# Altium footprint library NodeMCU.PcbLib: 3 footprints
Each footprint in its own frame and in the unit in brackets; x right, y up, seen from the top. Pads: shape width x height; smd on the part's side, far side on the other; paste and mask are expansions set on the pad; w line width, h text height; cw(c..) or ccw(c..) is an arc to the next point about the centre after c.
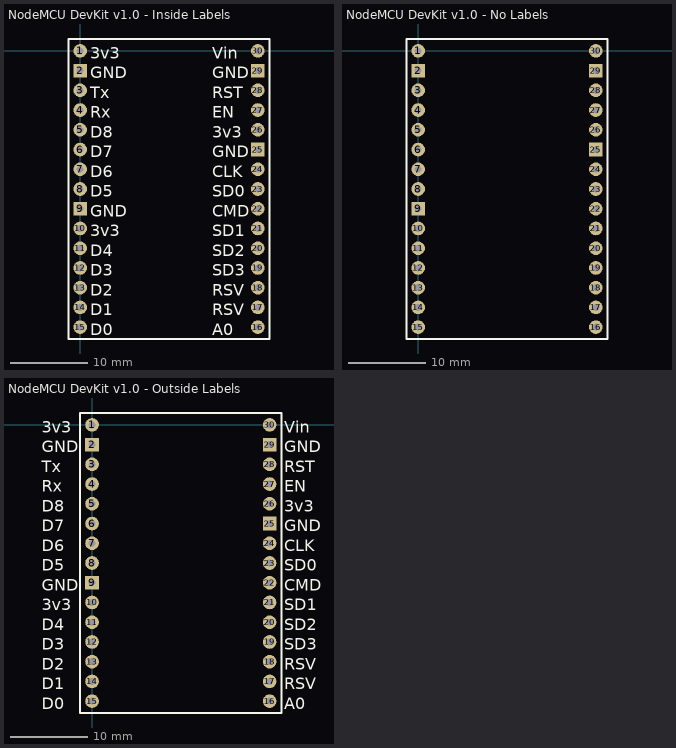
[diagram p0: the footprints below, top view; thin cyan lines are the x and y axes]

## NodeMCU DevKit v1.0 - Inside Labels [mil]
pads (30):
  round 69 hole 35: 1(0,0) 3(0,-200) 4(0,-300) 5(0,-400) 6(0,-500) 7(0,-600) 8(0,-700) 10(0,-900) 11(0,-1000) 12(0,-1100) 13(0,-1200) 14(0,-1300) 15(0,-1400) 16(900,-1400) 17(900,-1300) 18(900,-1200) 19(900,-1100) 20(900,-1000) 21(900,-900) 22(900,-800) 23(900,-700) 24(900,-600) 26(900,-400) 27(900,-300) 28(900,-200) 30(900,0)
  rect 69x69 hole 35: 2(0,-100) 9(0,-800) 25(900,-500) 29(900,-100)
Top Overlay:
  lines w10: -60,-1460 -60,60 960,60 960,-1460 -60,-1460
  text "3v3" at 50,-39.99 h60
  text "GND" at 50,-139.99 h60
  text "Tx" at 50,-239.99 h60
  text "Rx" at 50,-339.99 h60
  text "D8" at 50,-439.99 h60
  text "D7" at 50,-539.99 h60
  text "D6" at 50,-639.99 h60
  text "D5" at 50,-739.99 h60
  text "GND" at 50,-839.99 h60
  text "3v3" at 50,-939.99 h60
  text "D4" at 50,-1039.99 h60
  text "D3" at 50,-1139.99 h60
  text "D2" at 50,-1239.99 h60
  text "D1" at 50,-1339.99 h60
  text "D0" at 50,-1439.99 h60
  text "A0" at 670,-1439.99 h60
  text "RSV" at 670,-1339.99 h60
  text "RSV" at 670,-1239.99 h60
  text "SD3" at 670,-1139.99 h60
  text "SD2" at 670,-1039.99 h60
  text "SD1" at 670,-939.99 h60
  text "CMD" at 670,-839.99 h60
  text "SD0" at 670,-739.99 h60
  text "CLK" at 670,-639.99 h60
  text "GND" at 670,-539.99 h60
  text "3v3" at 670,-439.99 h60
  text "EN" at 670,-339.99 h60
  text "RST" at 670,-239.99 h60
  text "GND" at 670,-139.99 h60
  text "Vin" at 670,-39.99 h60

## NodeMCU DevKit v1.0 - No Labels [mil]
pads (30):
  round 69 hole 35: 1(0,0) 3(0,-200) 4(0,-300) 5(0,-400) 6(0,-500) 7(0,-600) 8(0,-700) 10(0,-900) 11(0,-1000) 12(0,-1100) 13(0,-1200) 14(0,-1300) 15(0,-1400) 16(900,-1400) 17(900,-1300) 18(900,-1200) 19(900,-1100) 20(900,-1000) 21(900,-900) 22(900,-800) 23(900,-700) 24(900,-600) 26(900,-400) 27(900,-300) 28(900,-200) 30(900,0)
  rect 69x69 hole 35: 2(0,-100) 9(0,-800) 25(900,-500) 29(900,-100)
Top Overlay:
  lines w10: -60,-1460 -60,60 960,60 960,-1460 -60,-1460

## NodeMCU DevKit v1.0 - Outside Labels [mil]
pads (30):
  round 69 hole 35: 1(0,0) 3(0,-200) 4(0,-300) 5(0,-400) 6(0,-500) 7(0,-600) 8(0,-700) 10(0,-900) 11(0,-1000) 12(0,-1100) 13(0,-1200) 14(0,-1300) 15(0,-1400) 16(900,-1400) 17(900,-1300) 18(900,-1200) 19(900,-1100) 20(900,-1000) 21(900,-900) 22(900,-800) 23(900,-700) 24(900,-600) 26(900,-400) 27(900,-300) 28(900,-200) 30(900,0)
  rect 69x69 hole 35: 2(0,-100) 9(0,-800) 25(900,-500) 29(900,-100)
Top Overlay:
  lines w10: -60,-1460 960,-1460 960,60 -60,60 -60,-1460
  text "D0" at -255,-1439.99 h60
  text "D1" at -255,-1339.99 h60
  text "D2" at -255,-1239.99 h60
  text "D3" at -255,-1139.99 h60
  text "D4" at -255,-1039.99 h60
  text "3v3" at -255,-939.99 h60
  text "GND" at -255,-839.99 h60
  text "D5" at -255,-739.99 h60
  text "D6" at -255,-639.99 h60
  text "D7" at -255,-539.99 h60
  text "D8" at -255,-439.99 h60
  text "Rx" at -255,-339.99 h60
  text "Tx" at -255,-239.99 h60
  text "GND" at -255,-139.99 h60
  text "3v3" at -255,-39.99 h60
  text "Vin" at 975,-39.99 h60
  text "GND" at 975,-139.99 h60
  text "RST" at 975,-239.99 h60
  text "EN" at 975,-339.99 h60
  text "3v3" at 975,-439.99 h60
  text "GND" at 975,-539.99 h60
  text "CLK" at 975,-639.99 h60
  text "SD0" at 975,-739.99 h60
  text "CMD" at 975,-839.99 h60
  text "SD1" at 975,-939.99 h60
  text "SD2" at 975,-1039.99 h60
  text "SD3" at 975,-1139.99 h60
  text "RSV" at 975,-1239.99 h60
  text "RSV" at 975,-1339.99 h60
  text "A0" at 975,-1439.99 h60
